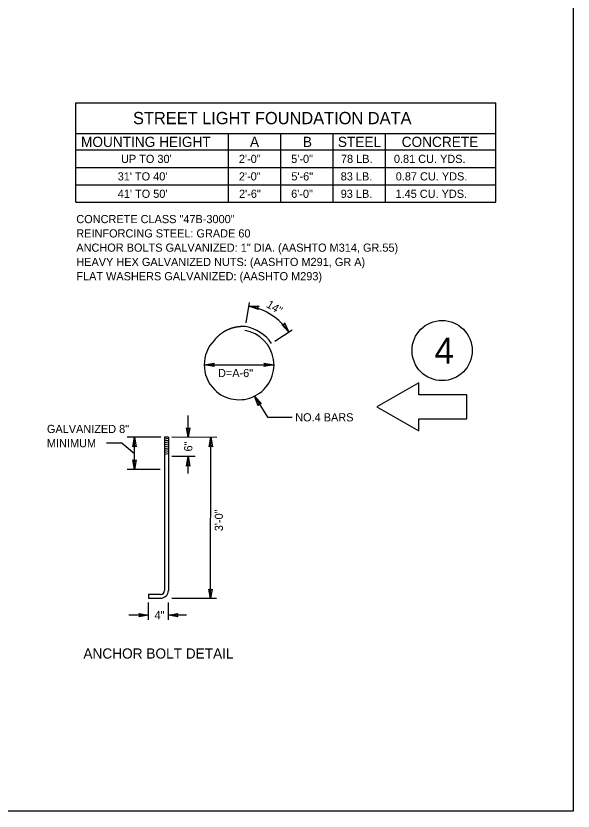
# Model space of a CAD drawing. Extents: x 99836 to 115004, y 99786 to 102182.
# Drawn here: x 102357 to 103176, y 99886 to 101055 of the extents above; entities that cross this region are included whole.
import ezdxf

# ---------------------------------------------------------------- set-up
doc = ezdxf.new("R2010")
doc.units = 0
for name, color, linetype in [('Border Organizer Shape', 7, 'Continuous'), ('Default', 7, 'Continuous'), ('Notes General Notes', 7, 'Continuous')]:
    doc.layers.add(name, color=color, linetype=linetype)

msp = doc.modelspace()

# ---------------------------------------------------------------- linework, layer by layer
at = {"layer": 'Border Organizer Shape'}
for p, q in [((102445.5, 100927.4), (103062.4, 100927.4)), ((102445.5, 100781.1), (102445.5, 100927.4)), ((103062.4, 100781.1), (103062.4, 100927.4)), ((102445.5, 100882.4), (103062.4, 100882.4)), ((102669.6, 100781.1), (102669.6, 100882.4)), ((102746.7, 100781.1), (102746.7, 100882.4)), ((102823.4, 100781.1), (102823.4, 100882.4)), ((102900.1, 100781.1), (102900.1, 100882.4)), ((102445.5, 100858.1), (103062.4, 100858.1)), ((102445.5, 100832.4), (103062.4, 100832.4)), ((102445.5, 100806.7), (103062.4, 100806.7)), ((102445.5, 100781.1), (103062.4, 100781.1)), ((102695.5, 100604.1), (102700.5, 100634)), ((102737.7, 100576.8), (102763, 100593.5)), ((102633.9, 100542.1), (102736.5, 100542.1)), ((102610.5, 100435.6), (102610.5, 100467.5)), ((102513.4, 100426.8), (102490.1, 100426.9)), ((102513.4, 100426.8), (102531.6, 100411.9)), ((102570.1, 100435.6), (102520.8, 100435.6)), ((102531.6, 100388.3), (102531.6, 100435.6)), ((102575.6, 100435.6), (102575.6, 100416.7)), ((102581.3, 100435.6), (102575.6, 100435.6)), ((102581.3, 100433.8), (102575.6, 100432.9)), ((102581.3, 100431.1), (102575.6, 100430.2)), ((102581.3, 100428.3), (102575.6, 100427.4)), ((102581.2, 100425.5), (102575.6, 100424.6)), ((102581.3, 100435.6), (102581.3, 100416.7)), ((102652.4, 100435.5), (102586.5, 100435.6)), ((102643.3, 100198.4), (102643.5, 100435.6)), ((102581.2, 100419.8), (102575.5, 100418.9)), ((102581.2, 100422.5), (102575.6, 100421.6)), ((102581.2, 100417), (102575.6, 100416.1)), ((102575.6, 100416.7), (102575.6, 100210.4)), ((102581.1, 100414.2), (102575.6, 100413.3)), ((102581.3, 100416.7), (102581.3, 100210.4)), ((102581.1, 100411.3), (102575.6, 100410.3)), ((102620.6, 100407.2), (102586.5, 100407.2)), ((102610.5, 100382.2), (102610.5, 100407.2)), ((102569.4, 100388.3), (102520.8, 100388.3)), ((102552, 100204.8), (102569.9, 100204.8)), ((102552, 100204.8), (102552, 100199.1)), ((102551.9, 100167.2), (102552, 100192.9)), ((102552, 100199.1), (102569.9, 100199.1)), ((102581.3, 100167.2), (102581.3, 100192.9)), ((102652.2, 100198.4), (102586.3, 100198.4)), ((102552, 100174.2), (102523, 100174.2)), ((102607.9, 100174.1), (102581.3, 100174.2))]:
    msp.add_line(p, q, dxfattribs=at)
for points in [[(102713.8, 100623.5), (102699.6, 100628.4), (102714.6, 100628.4), (102711.9, 100626.3)], [(102752.1, 100604.1), (102758.2, 100590.3), (102747.9, 100601.3), (102751.3, 100600.7)], [(102648.7, 100539.6), (102633.9, 100542.1), (102648.7, 100544.6), (102646.4, 100542.1)], [(102721.7, 100544.6), (102736.5, 100542.1), (102721.7, 100539.6), (102724, 100542.1)], [(102713.3, 100482.1), (102707.6, 100496), (102717.5, 100484.7), (102714.2, 100485.4)], [(102612.9, 100449.7), (102610.5, 100435.6), (102608.1, 100449.7), (102610.5, 100447.5)], [(102529.2, 100421.5), (102531.6, 100435.6), (102534, 100421.5), (102531.6, 100423.7)], [(102641.1, 100421.5), (102643.5, 100435.6), (102645.9, 100421.4), (102643.5, 100423.7)], [(102534, 100402.4), (102531.6, 100388.3), (102529.2, 100402.4), (102531.6, 100400.2)], [(102608.1, 100393.1), (102610.5, 100407.2), (102612.9, 100393.1), (102610.5, 100395.3)], [(102645.7, 100212.5), (102643.3, 100198.4), (102640.9, 100212.5), (102643.3, 100210.2)], [(102537.9, 100176.6), (102552, 100174.2), (102537.9, 100171.8), (102540.1, 100174.2)], [(102595.4, 100171.7), (102581.3, 100174.2), (102595.4, 100176.5), (102593.2, 100174.1)]]:
    msp.add_lwpolyline(points, close=True, dxfattribs=at)
msp.add_lwpolyline([(102707.6, 100496), (102726.8, 100465), (102763.2, 100465)], dxfattribs=at)
for centre, radius, start, end in [((102685.2, 100542.1), 87.4, 33.427, 80.5536), ((102685.2, 100542.1), 51.3, 224.9925, 80.5568), ((102685.2, 100542.1), 57, 33.4279, 80.5568), ((102685.2, 100542.1), 51.3, 134.9925, 224.9925), ((102569.9, 100210.4), 5.68, 270, 360), ((102569.9, 100210.4), 11.4, 270, 360)]:
    msp.add_arc(centre, radius, start, end, dxfattribs=at)
msp.add_spline([(102694.5, 100598.4), (102693.7, 100598.4), (102693, 100598.5), (102692.2, 100598.5), (102691.4, 100598.5), (102690.6, 100598.5), (102689.8, 100598.4), (102689, 100598.4), (102688.2, 100598.4), (102687.4, 100598.3), (102686.6, 100598.2), (102685.8, 100598.2), (102685, 100598.1), (102684.2, 100598), (102683.4, 100597.9), (102682.7, 100597.8), (102681.9, 100597.7), (102681.1, 100597.6), (102680.3, 100597.4), (102679.5, 100597.2), (102678.8, 100597), (102677.9, 100596.8), (102677.2, 100596.7), (102676.5, 100596.5), (102675.7, 100596.2), (102674.9, 100596), (102674.1, 100595.8), (102673.4, 100595.6), (102672.7, 100595.3), (102671.9, 100595), (102671.1, 100594.7), (102670.4, 100594.4), (102669.6, 100594.1), (102668.9, 100593.8), (102668.2, 100593.5), (102667.5, 100593.1), (102666.7, 100592.7), (102666.1, 100592.4), (102665.4, 100592), (102664.6, 100591.6), (102664, 100591.3), (102663.3, 100590.9), (102662.5, 100590.5), (102661.9, 100590.1), (102661.3, 100589.6), (102660.6, 100589.2), (102659.9, 100588.7), (102659.3, 100588.3), (102658.6, 100587.8), (102658, 100587.4), (102657.3, 100586.8), (102656.8, 100586.4), (102656.2, 100585.8), (102655.5, 100585.4), (102655, 100584.8), (102654.3, 100584.3), (102653.8, 100583.7), (102653.2, 100583.2), (102652.7, 100582.6), (102652, 100582), (102651.5, 100581.4), (102651, 100580.9), (102650.5, 100580.2), (102650, 100579.6), (102649.4, 100579.1), (102648.9, 100578.4)], degree=3, dxfattribs=at)
at = {"layer": 'Default'}
msp.add_lwpolyline([(99976.3, 102085.7), (103176, 102085.7), (103176, 99886.1), (99976.3, 99886.1)], close=True, dxfattribs=at)
at = {"layer": 'Notes General Notes'}
msp.add_lwpolyline([(102887.6, 100480.4), (102949.1, 100444.9), (102949.1, 100462.6), (103020, 100462.6), (103020, 100498.1), (102949.1, 100498.1), (102949.1, 100515.8)], close=True, dxfattribs=at)
msp.add_circle((102983.5, 100563.1), 44.2, dxfattribs=at)

# ---------------------------------------------------------------- texts
at = {"layer": 'Border Organizer Shape'}
for s, height, p in [('STREET LIGHT FOUNDATION DATA', 18, (102529.3, 100895.9)), ('MOUNTING HEIGHT', 15, (102452.9, 100862.4)), ('A', 15, (102701.2, 100862.4)), ('B', 15, (102778.9, 100862.4)), ('STEEL', 15, (102830.3, 100862.4)), ('CONCRETE', 15, (102924.1, 100862.4)), ("UP TO 30'", 12, (102511.7, 100838.9)), ('2\'-0"', 12, (102684.9, 100838.9)), ('5\'-0"', 12, (102761.8, 100838.9)), ('78 LB.', 12, (102834.9, 100838.9)), ('0.81 CU. YDS.', 12, (102912.7, 100838.9)), ("31' TO 40'", 12, (102506.8, 100813.2)), ('2\'-0"', 12, (102684.9, 100813.2)), ('5\'-6"', 12, (102762, 100813.2)), ('83 LB.', 12, (102834.5, 100813.2)), ('0.87 CU. YDS.', 12, (102915.4, 100813.2)), ("41' TO 50'", 12, (102506.9, 100787.6)), ('2\'-6"', 12, (102685.1, 100787.6)), ('6\'-0"', 12, (102761.7, 100787.6)), ('93 LB.', 12, (102834.5, 100787.6)), ('1.45 CU. YDS.', 12, (102915, 100787.6)), ('CONCRETE CLASS "47B-3000"', 12, (102446, 100750.4)), ('REINFORCING STEEL: GRADE 60', 12, (102446, 100729.4)), ('ANCHOR BOLTS GALVANIZED: 1" DIA. (AASHTO M314, GR.55)', 12, (102446, 100708.4)), ('HEAVY HEX GALVANIZED NUTS: (AASHTO M291, GR A)', 12, (102446, 100687.4)), ('FLAT WASHERS GALVANIZED: (AASHTO M293)', 12, (102446, 100666.4)), ('GALVANIZED 8"', 12, (102402.8, 100441.9)), ('MINIMUM ', 12, (102402.8, 100420.9)), ('4"', 12, (102560.9, 100168.2)), ('ANCHOR BOLT DETAIL', 15, (102456.4, 100110.3))]:
    msp.add_text(s, height=height, dxfattribs=at).set_placement(p)
for s, rotation, p in [('14"', 328.8322, (102724.1, 100627.7)), ('D=A-6"', 359.9925, (102654.2, 100524.1)), (' NO.4 BARS', 359.9925, (102763.2, 100459)), ('6"', 90, (102616.5, 100414.8)), ('3\'-0"', 90, (102661.4, 100297.6))]:
    msp.add_text(s, height=12, rotation=rotation, dxfattribs=at).set_placement(p)
at = {"layer": 'Notes General Notes'}
msp.add_text('4', height=38.3, dxfattribs=at).set_placement((102972.3, 100544))

doc.saveas('drawing.dxf')
